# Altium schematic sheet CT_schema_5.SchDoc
size 255 x 159 mm
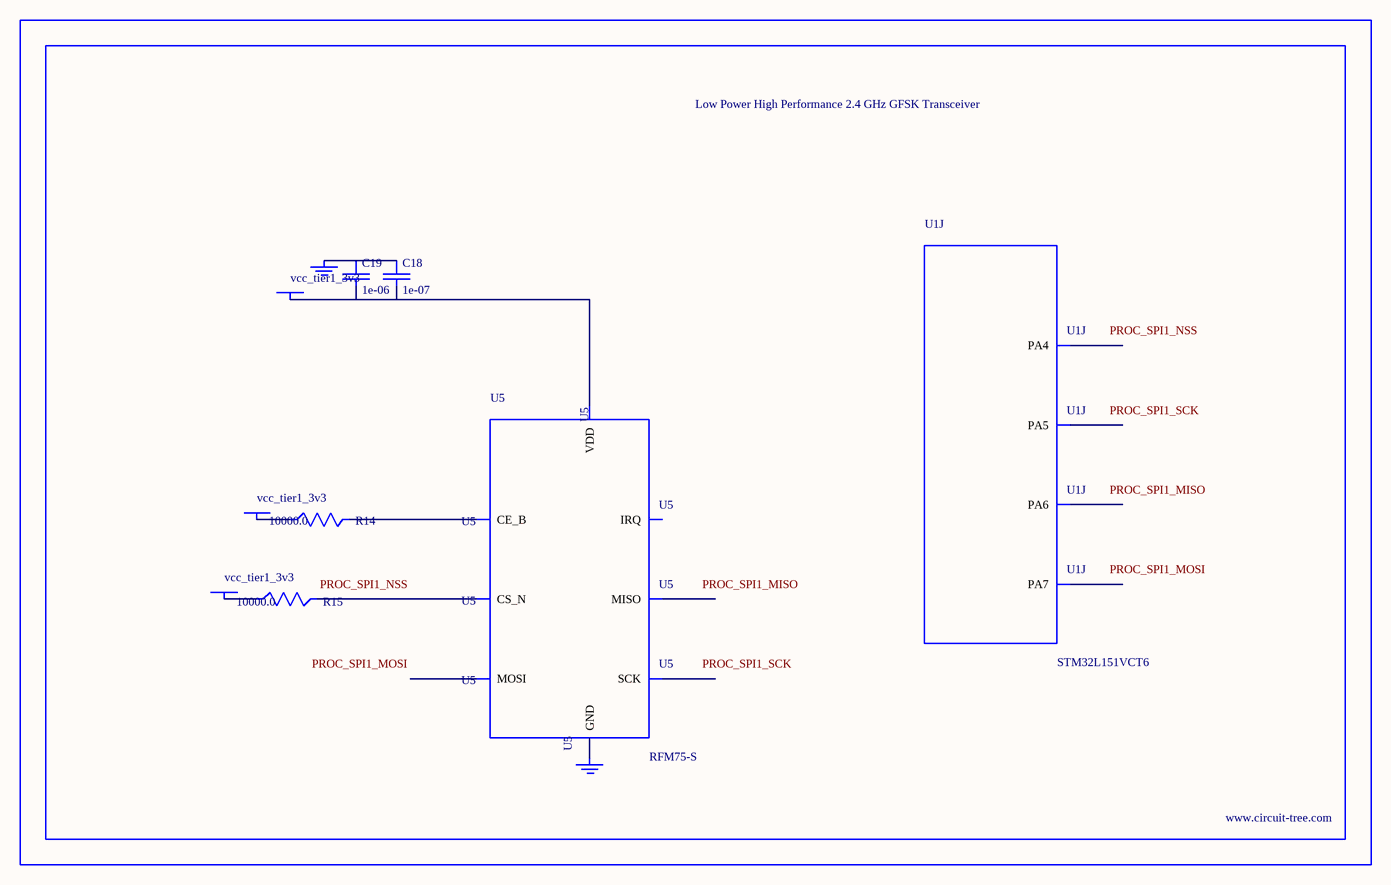
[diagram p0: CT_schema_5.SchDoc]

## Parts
BORDER4  (no value)
C18  1e-07  [C0402]
C19  1e-06  [C0603]
GND_INSTANCE_4_0  (no value)
GND_INSTANCE_4_1  (no value)
POWER_INSTANCE_4_0  vcc_tier1_3v3
POWER_INSTANCE_4_1  vcc_tier1_3v3
POWER_INSTANCE_4_2  vcc_tier1_3v3
R14  10000.0  [R0603]
R15  10000.0  [R0603]
U1  STM32L151VCT6  [LQFP100]  (part J of 11)
U5  RFM75-S  [RFM75-S]

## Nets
NetC18_1: C18.1 C19.1 GND_INSTANCE_4_0.0(GND)
NetC18_2: C18.2 C19.2 POWER_INSTANCE_4_0.0(PWR) U5.2(VDD)
NetGND_INSTANCE_4_1_0: GND_INSTANCE_4_1.0(GND) U5.1(GND)
NetPOWER_INSTANCE_4_1_0: POWER_INSTANCE_4_1.0(PWR) R14.1
NetPOWER_INSTANCE_4_2_0: POWER_INSTANCE_4_2.0(PWR) R15.1
NetR14_2: R14.2 U5.3(CE_B)
NetR15_2: R15.2 U5.4(CS_N)

Not connected (* = marked no-connect by the designer): U1 29(PA4) 30(PA5) 31(PA6) 32(PA7); U5 5(SCK) 6(MOSI) 7(MISO) 8(IRQ)

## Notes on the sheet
- Labels drawn without touching a wire or pin: PROC_SPI1_MISO, PROC_SPI1_MOSI, PROC_SPI1_NSS, PROC_SPI1_SCK

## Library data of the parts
BORDER4 = BORDER_PAGE4
C18 = C0402C104K3RACTU
C19 = C0603C105K3RACTU
GND_INSTANCE_4_0 GND_INSTANCE_4_1 = GND
POWER_INSTANCE_4_0-POWER_INSTANCE_4_2 = PWR
R14 R15 = RC0603JR-0710KL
